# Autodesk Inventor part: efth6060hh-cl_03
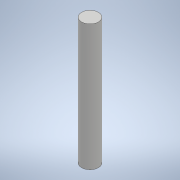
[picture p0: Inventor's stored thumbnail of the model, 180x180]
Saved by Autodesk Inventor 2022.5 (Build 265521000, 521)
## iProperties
Part Number: efth6060hh-cl_03
Material: 一般
Document SubType Name: Modeling
Designer: ImaoCorp
Density: 1 g/cm^3
Appearance: 既定
Author: ImaoCorp
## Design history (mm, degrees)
feature "efth6060hh-cl_03"
node "ソリッド1"
